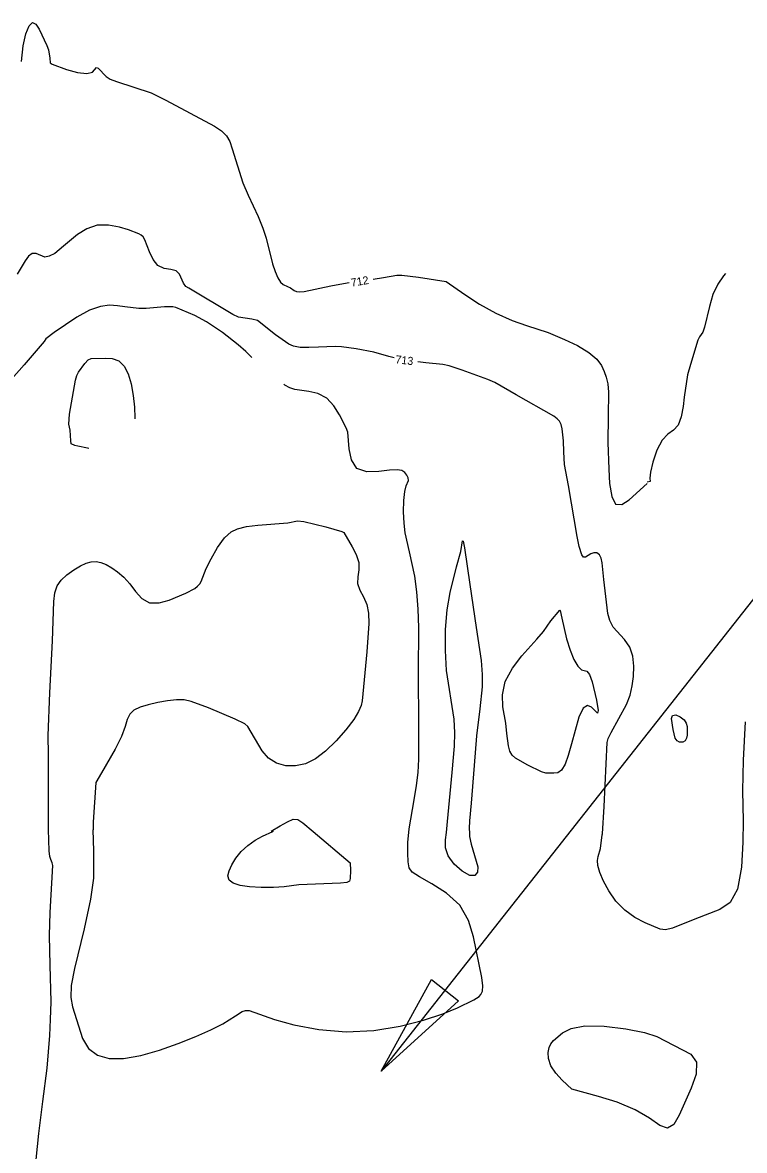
# Model space of a CAD drawing. Extents: x -468548933 to 3387700, y -306089263 to 1207014.
# Drawn here: x 1840538 to 1840899, y 537416 to 537979 of the extents above; entities that cross this region are included whole.
import ezdxf

# ---------------------------------------------------------------- set-up
doc = ezdxf.new("R2010")
doc.units = 0
for name, color, linetype in [('DT_X_Contour_Minor', 7, 'Continuous'), ('Level 19', 7, 'Continuous'), ('Level 40', 7, 'Continuous')]:
    doc.layers.add(name, color=color, linetype=linetype)

msp = doc.modelspace()

# ---------------------------------------------------------------- linework, layer by layer
at = {"layer": 'DT_X_Contour_Minor'}
for points in [[(1840537.76, 537959.88), (1840538.71, 537967.56), (1840540.02, 537973.65), (1840541.59, 537977.64), (1840543.29, 537979.26), (1840545, 537978.42), (1840546.63, 537975.97), (1840550.54, 537967.78), (1840551.32, 537965.55), (1840551.98, 537961.53), (1840552.22, 537959.18), (1840553.19, 537958.44), (1840560.38, 537955.86), (1840565.82, 537954.36), (1840570.53, 537953.74), (1840573.32, 537954.5), (1840575.38, 537956.82), (1840576.2, 537956.49), (1840580.1, 537952.29), (1840582.21, 537951.05), (1840585.25, 537949.81), (1840602.61, 537944.08), (1840610.08, 537940.43), (1840634.31, 537927.53), (1840637.9, 537925.08), (1840640.33, 537922.63), (1840641.95, 537919.79), (1840643.26, 537916.17), (1840648.44, 537899.21)], [(1840648.44, 537899.21), (1840651.26, 537893.09), (1840656.19, 537882.31), (1840658.51, 537876.5), (1840660.12, 537871.48), (1840663.35, 537858.75), (1840664.63, 537854.88), (1840665.99, 537851.73), (1840667.37, 537849.62), (1840668.69, 537848.37), (1840670.78, 537847.37), (1840672.36, 537846.74), (1840674.2, 537845.38), (1840675.38, 537844.83), (1840676.88, 537844.66), (1840679.11, 537844.91), (1840692.49, 537847.69), (1840700.76, 537849.26), (1840701.76, 537849.36)], [(1840724.19, 537811.67), (1840721.53, 537812.33), (1840713.99, 537814.51), (1840705.25, 537816.25), (1840697.89, 537817.26), (1840694.71, 537817.44), (1840686.41, 537817.12), (1840681.48, 537816.88), (1840677.11, 537816.95), (1840673.91, 537817.54), (1840671.54, 537818.59), (1840664.82, 537823.29), (1840655.77, 537830.35), (1840653.08, 537831.12), (1840646.32, 537832.09), (1840643.58, 537833.45), (1840621.51, 537846.51), (1840620.07, 537847.45), (1840618.78, 537849), (1840616.89, 537853.5), (1840615.24, 537855.2), (1840612.53, 537855.91), (1840609.24, 537856.43), (1840606.08, 537857.84), (1840603.61, 537860.89), (1840601.8, 537864.78), (1840599.49, 537870.75), (1840598.63, 537872.15), (1840597.7, 537873), (1840596.47, 537873.74), (1840591.39, 537875.66), (1840586.85, 537877.04), (1840581.39, 537878.06), (1840575.72, 537877.95), (1840570.44, 537876.17), (1840565.78, 537873.29), (1840558.75, 537867.46), (1840554.43, 537863.86), (1840551.61, 537862.49), (1840549.45, 537862.06), (1840545.07, 537863.95), (1840543.11, 537863.85), (1840541.33, 537862.5), (1840539.73, 537860.26), (1840535.64, 537853.46)], [(1840713.64, 537851.06), (1840718.81, 537851.91), (1840725.6, 537853.02), (1840728.1, 537853.1), (1840736.36, 537852.12), (1840750.16, 537849.88), (1840759.58, 537843.3), (1840766.83, 537838.63), (1840775, 537834.07), (1840783.17, 537830.46), (1840790.42, 537827.88), (1840801.24, 537824.46), (1840809.44, 537820.9), (1840815.82, 537817.84), (1840821.62, 537814.46), (1840825.56, 537811.14), (1840827.9, 537807.96), (1840829.31, 537804.96), (1840830.31, 537802.06), (1840831.01, 537798.79), (1840831.38, 537794.58), (1840831.3, 537782.63), (1840831.13, 537769.49), (1840831.52, 537756.17), (1840831.98, 537748.9), (1840832.99, 537742.52), (1840834.94, 537738.69), (1840838.05, 537738.51), (1840841.67, 537740.8), (1840850.72, 537748.88)], [(1840889.97, 537853.82), (1840888.86, 537852.7), (1840886, 537848.52), (1840883.62, 537843.33), (1840881.84, 537837.37), (1840879.49, 537827.02), (1840878.53, 537824.49), (1840876.84, 537822.21), (1840876.14, 537820.49), (1840872.37, 537808.37), (1840870.9, 537803.16), (1840869.32, 537792.14), (1840868.74, 537787.4), (1840867.81, 537782.34), (1840866.26, 537778.17), (1840863.93, 537775.64), (1840861.11, 537773.66), (1840858.21, 537770.65), (1840855.61, 537765.6), (1840853.57, 537759.67), (1840852.37, 537754.59), (1840852.12, 537751.64), (1840852.31, 537749.98), (1840850.73, 537749.68)], [(1840653.03, 537811.95), (1840650.08, 537814.83), (1840646.26, 537818.24), (1840638.34, 537824.33), (1840630.28, 537829.66), (1840624.48, 537832.95), (1840615.02, 537836.93), (1840613.43, 537837.24), (1840609.33, 537837.15), (1840600.1, 537836.31), (1840596.56, 537836.33), (1840589.52, 537837.23), (1840585.83, 537837.75), (1840581.84, 537837.97), (1840577.28, 537837.4), (1840571.83, 537835.51), (1840565.46, 537832.04), (1840554.17, 537824.45), (1840549.95, 537821.19), (1840549.15, 537819.95), (1840539.14, 537808.26), (1840532.74, 537801.09)], [(1840571.54, 537766.39), (1840570.9, 537766.65), (1840566.06, 537767.56), (1840564.44, 537768.01), (1840562.71, 537768.85), (1840562.51, 537770.2), (1840562.16, 537775.57), (1840561.44, 537778.67), (1840561.89, 537783.51), (1840564.86, 537800.62), (1840565.46, 537802.85), (1840566.31, 537804.5), (1840569.46, 537808.97), (1840571.19, 537810.68), (1840572.71, 537811.41), (1840579.61, 537811.52), (1840583.1, 537811.33), (1840586.42, 537810.2), (1840589.09, 537807.64), (1840591.11, 537803.72), (1840592.62, 537798.7), (1840593.71, 537792.91), (1840594.36, 537787.02), (1840594.5, 537781.81), (1840594.46, 537781.2)], [(1840828.34, 537573.88), (1840829.25, 537587.56), (1840830.69, 537619.54), (1840831.28, 537621.57), (1840832.65, 537624.55), (1840840.36, 537638.49), (1840842.18, 537643.21), (1840843.28, 537647.8), (1840843.85, 537652.55), (1840844, 537657.63), (1840843.49, 537662.69), (1840842, 537667.23), (1840839.41, 537670.93), (1840833.68, 537677.16), (1840832.01, 537680.48), (1840831.14, 537684.02), (1840829.07, 537700.98), (1840828.19, 537709.28), (1840827.7, 537711.65), (1840826.87, 537713.38), (1840825.6, 537714.25), (1840824.08, 537714.34), (1840822.52, 537713.81), (1840819.93, 537712.14), (1840818.92, 537712.12), (1840818.08, 537713.26), (1840816.78, 537717.54), (1840815.7, 537722.47), (1840811.47, 537747.97), (1840809.45, 537758.5), (1840809.08, 537764.71), (1840808.96, 537770.27), (1840808.2, 537776.2), (1840807.66, 537778.38), (1840806.89, 537780.03), (1840805.75, 537781.33), (1840804.02, 537782.53), (1840785.29, 537793.25), (1840774.52, 537799.34), (1840771.09, 537800.87), (1840758.19, 537805.65), (1840751.74, 537807.72), (1840748.51, 537808.36), (1840740.04, 537809.32), (1840736.05, 537809.77)], [(1840731.54, 537574.65), (1840731.64, 537576.35), (1840734.19, 537590.89), (1840735.45, 537597.98), (1840736.22, 537604.56), (1840736.57, 537611.26), (1840736.51, 537628.06), (1840736.31, 537654.38), (1840736.47, 537676.95), (1840736.18, 537686.08), (1840735.55, 537694.9), (1840734.53, 537702.64), (1840731.94, 537714.86), (1840729.77, 537724.26), (1840729.12, 537729.2), (1840728.88, 537734.83), (1840729.02, 537740.44), (1840729.5, 537745), (1840730.23, 537747.82), (1840731.36, 537750.5), (1840731.22, 537751.78), (1840730.57, 537753.17), (1840729.52, 537754.43), (1840728.07, 537755.36), (1840725.74, 537755.79), (1840721.95, 537755.61), (1840716.48, 537754.9), (1840710.51, 537754.74), (1840705.59, 537756.43), (1840702.85, 537760.74), (1840701.77, 537766.35), (1840701.01, 537774.63), (1840700.23, 537776.83), (1840696.89, 537783.3), (1840694.1, 537787.75), (1840690.48, 537791.56), (1840686.09, 537793.85), (1840681.54, 537794.94), (1840674.53, 537795.88), (1840672.1, 537796.67), (1840669.58, 537798.09), (1840669.02, 537798.52)], [(1840551.38, 537576.1), (1840551.25, 537586.98), (1840551.26, 537613.46), (1840551.15, 537623.06), (1840552.03, 537644.35), (1840553.36, 537670.28), (1840553.92, 537690.05), (1840554.51, 537694.34), (1840555.66, 537697.75), (1840557.62, 537700.67), (1840560.53, 537703.37), (1840563.95, 537705.79), (1840567.32, 537707.75), (1840570.22, 537709.12), (1840572.74, 537709.86), (1840575.13, 537709.98), (1840577.56, 537709.49), (1840580.14, 537708.43), (1840582.92, 537706.85), (1840585.9, 537704.78), (1840588.97, 537702.15), (1840591.97, 537698.86), (1840594.85, 537695), (1840597.96, 537691.46), (1840601.79, 537689.3), (1840606.59, 537689.27), (1840611.74, 537690.69), (1840619.99, 537694.12), (1840624.43, 537696.43), (1840625.87, 537697.57), (1840626.95, 537698.75), (1840627.69, 537699.95), (1840630.22, 537706.43), (1840632.65, 537711.38), (1840635.84, 537716.95), (1840639.34, 537721.77), (1840642.74, 537724.77), (1840645.8, 537726.29), (1840650.39, 537727.42), (1840655.97, 537728.08), (1840671.02, 537729.34), (1840675.88, 537730.22), (1840678.94, 537729.94), (1840690.04, 537727.35), (1840697.98, 537725.02), (1840699.09, 537724.47), (1840703.26, 537717.28), (1840705.26, 537713.45), (1840706.52, 537709.46), (1840706.53, 537705.75), (1840705.99, 537702.32), (1840705.92, 537699.01), (1840707.04, 537695.71), (1840708.84, 537692.25), (1840710.5, 537688.46), (1840711.38, 537684.16), (1840711.52, 537679), (1840710.52, 537664.88), (1840708.21, 537640.37), (1840707.64, 537638.03), (1840706.38, 537635.08), (1840703.95, 537631.11), (1840700.07, 537625.95), (1840695.19, 537620.33), (1840689.92, 537615.21), (1840684.8, 537611.39), (1840679.83, 537608.96), (1840674.89, 537607.81), (1840669.96, 537607.88), (1840665.31, 537609.17), (1840661.31, 537611.71), (1840658.2, 537615.37), (1840651.05, 537627.51), (1840649.43, 537628.79), (1840644.75, 537631.22), (1840631.4, 537636.87), (1840622.71, 537640.08), (1840619.2, 537640.81), (1840615.4, 537640.92), (1840610.85, 537640.43), (1840605.92, 537639.52), (1840601.2, 537638.37), (1840597.19, 537637.12), (1840594.07, 537635.63), (1840591.94, 537633.69), (1840590.71, 537631.06), (1840589.65, 537627.45), (1840587.83, 537622.5), (1840584.68, 537616.19), (1840577.8, 537604.39), (1840575.05, 537599.47), (1840573.72, 537579.78), (1840573.63, 537575.92)], [(1840750.3, 537574.5), (1840750.94, 537580.08), (1840753.21, 537604.55), (1840754.38, 537617.74), (1840754.55, 537624.31), (1840754.13, 537631.14), (1840750.41, 537655.57), (1840749.82, 537665.57), (1840749.94, 537675.92), (1840750.76, 537685.8), (1840752.19, 537694.5), (1840755.45, 537707.25), (1840757.51, 537714.9), (1840758.38, 537720.22), (1840758.7, 537720.15), (1840759.4, 537716.86), (1840761.97, 537698.55), (1840765.13, 537677.06), (1840767.68, 537660.45), (1840768.29, 537653.47), (1840768.28, 537647.43), (1840767, 537636.31), (1840765.45, 537622.86), (1840764.23, 537608.04), (1840762.74, 537589.16), (1840761.89, 537580.44), (1840761.73, 537576.5), (1840761.84, 537574.41)], [(1840795.62, 537671.15), (1840798.89, 537674.97), (1840802.56, 537680.35), (1840807.04, 537685.74), (1840807.27, 537685.51), (1840808.07, 537681.65), (1840810.42, 537671.38), (1840812.15, 537665.69), (1840814.12, 537661.04), (1840816.14, 537657.73), (1840817.96, 537655.9), (1840820.63, 537655.13), (1840821.84, 537653.58), (1840823.17, 537649.86), (1840825.44, 537640.62), (1840826.18, 537635.53), (1840825.93, 537634.15), (1840822.96, 537637.17), (1840820.88, 537638.02), (1840818.68, 537636.7), (1840816.6, 537632.24), (1840812.95, 537618.91), (1840811.29, 537613.08), (1840809.65, 537608.66), (1840807.9, 537605.78), (1840805.99, 537604.45), (1840804.12, 537604.14), (1840800, 537604.24), (1840797.94, 537604.87), (1840790.99, 537608.23), (1840784.91, 537611.71), (1840783.16, 537613.26), (1840782.03, 537615.23), (1840781.31, 537617.95), (1840780.61, 537624.01), (1840780.1, 537629.13), (1840778.63, 537637.37), (1840778.36, 537643.31), (1840779.74, 537649.94), (1840783.4, 537656.74), (1840788.13, 537662.91), (1840795.62, 537671.15)], [(1840899.7, 537629.84), (1840898.72, 537610.71), (1840898.37, 537595.42), (1840898.76, 537580.41), (1840898.64, 537569.8), (1840897.88, 537557.24), (1840895.87, 537546.29), (1840892.17, 537539.6), (1840887.06, 537536.12), (1840874.56, 537531.28), (1840863.39, 537526.7), (1840859.93, 537525.94), (1840857.21, 537526.3), (1840849.71, 537529.42), (1840844.59, 537532.09), (1840839.5, 537535.71), (1840835.11, 537540.3), (1840831.58, 537545.37), (1840828.92, 537550.3), (1840827.13, 537554.55), (1840826.13, 537558), (1840825.85, 537560.63), (1840826.15, 537562.53), (1840827.47, 537566.51), (1840828.31, 537573.36), (1840828.35, 537573.88)], [(1840870.76, 537625.35), (1840870.73, 537623.12), (1840870.47, 537621.65), (1840869.76, 537620.4), (1840868.5, 537619.72), (1840866.99, 537619.7), (1840865.66, 537620.35), (1840864.81, 537621.66), (1840863.8, 537626.04), (1840862.92, 537631.45), (1840863.44, 537633.1), (1840865.07, 537633.32), (1840867.24, 537632.41), (1840869.18, 537630.86), (1840870.27, 537629.14), (1840870.69, 537627.53), (1840870.76, 537625.35)], [(1840662.61, 537575.21), (1840667.26, 537577.84), (1840670.83, 537579.95), (1840673.76, 537581.17), (1840676.07, 537581), (1840678.54, 537579.36), (1840683.73, 537575.04)], [(1840544.41, 537404.68), (1840546.42, 537424.15), (1840548.41, 537440.22), (1840550.62, 537456.86), (1840551.95, 537473.21), (1840552.4, 537481.13), (1840552.61, 537489.94), (1840552.17, 537508.27), (1840551.82, 537523.1), (1840552.21, 537534.59), (1840553.41, 537558.05), (1840553.11, 537559.49), (1840552.42, 537561.01), (1840552, 537562.59), (1840551.63, 537565.43), (1840551.25, 537576.1)], [(1840573.56, 537575.92), (1840573.78, 537565.42), (1840573.78, 537551.83), (1840572.34, 537541.25), (1840569.11, 537526.36), (1840564.29, 537506.68), (1840562.72, 537498.17), (1840562.51, 537492.1), (1840563.34, 537487.52), (1840568.34, 537471.72), (1840571.38, 537466.69), (1840575.78, 537463.28), (1840581.61, 537461.62), (1840588.9, 537461.62), (1840597.51, 537463.14), (1840606.86, 537465.78), (1840616.25, 537469.07), (1840625, 537472.58), (1840632.59, 537475.98), (1840638.49, 537478.96), (1840644.84, 537483.01), (1840648.13, 537485.21), (1840649.81, 537485.68), (1840651.68, 537485.57), (1840664.27, 537481.13), (1840674.09, 537478.48), (1840686.47, 537476.12), (1840700.16, 537474.97), (1840714, 537475.69), (1840727.14, 537477.88), (1840738.84, 537480.86), (1840748.46, 537484.03), (1840755.86, 537486.97), (1840764.1, 537490.9), (1840766.68, 537492.68), (1840767.6, 537493.66), (1840768.33, 537495.25), (1840768.55, 537497.93), (1840768.02, 537502.06), (1840763.9, 537522.45), (1840761.35, 537530.66), (1840756.99, 537538.21), (1840750.4, 537544.33), (1840743.03, 537549), (1840736.81, 537552.39), (1840733.17, 537554.78), (1840731.62, 537556.96), (1840731.15, 537559.86), (1840730.97, 537564.17), (1840731.07, 537569.77), (1840731.5, 537574.65)], [(1840683.76, 537575.04), (1840702.2, 537559.46), (1840702.33, 537555.55), (1840702.26, 537551.58), (1840701.85, 537550.31), (1840700.47, 537549.58), (1840697.4, 537549.23), (1840676.51, 537548.37), (1840669.26, 537547.45), (1840663.9, 537547.16), (1840657.76, 537547.11), (1840651.87, 537547.39), (1840647.12, 537548.06), (1840643.72, 537549.18), (1840641.71, 537550.78), (1840641.08, 537552.87), (1840641.61, 537555.44), (1840643.01, 537558.41), (1840645.05, 537561.7), (1840647.69, 537565.04), (1840650.95, 537568.12), (1840654.73, 537570.69), (1840658.42, 537572.66), (1840663.59, 537575)], [(1840663.59, 537575), (1840663.85, 537575.2)], [(1840761.84, 537574.41), (1840761.93, 537572.64), (1840762.63, 537568.74), (1840766.08, 537557.47), (1840765.92, 537554.68), (1840764.58, 537553.05), (1840761.98, 537553.13), (1840758.24, 537555.24), (1840754.28, 537558.77), (1840751.22, 537562.86), (1840749.9, 537566.86), (1840749.88, 537570.87), (1840750.34, 537574.5)], [(1840813, 537446.27), (1840808.23, 537450.89), (1840805.13, 537454.31), (1840802.58, 537458.03), (1840801.31, 537461.57), (1840801.15, 537464.69), (1840801.67, 537467.2), (1840802.57, 537469.03), (1840803.88, 537470.56), (1840808.38, 537474.49), (1840812.65, 537476.62), (1840819.5, 537477.9), (1840829.28, 537477.77), (1840840.1, 537476.54), (1840849.48, 537474.69), (1840855.64, 537472.66), (1840872.65, 537463.83), (1840875.38, 537459.76), (1840875.16, 537453.84), (1840872.81, 537446.79), (1840866.79, 537433.28), (1840864.01, 537428.73), (1840860.9, 537426.87), (1840857.02, 537428.24), (1840851.82, 537431.78), (1840844.76, 537436.03), (1840835.73, 537439.79), (1840826.41, 537442.73), (1840813, 537446.27)]]:
    msp.add_lwpolyline(points, dxfattribs=at)
at = {"layer": 'Level 40'}
for p, q in [((1840943.63, 537741.72), (1840717.66, 537455.37)), ((1840717.66, 537455.37), (1840742.88, 537501.17)), ((1840742.88, 537501.17), (1840756.36, 537490.53)), ((1840756.36, 537490.53), (1840717.66, 537455.37))]:
    msp.add_line(p, q, dxfattribs=at)

# ---------------------------------------------------------------- texts
at = {"layer": 'Level 19'}
for s, rotation, p in [('712', 9.385, (1840702.89, 537847.25)), ('713', 353.4634, (1840724.67, 537809.06))]:
    msp.add_text(s, height=4, rotation=rotation, dxfattribs=at).set_placement(p)

doc.saveas('drawing.dxf')
